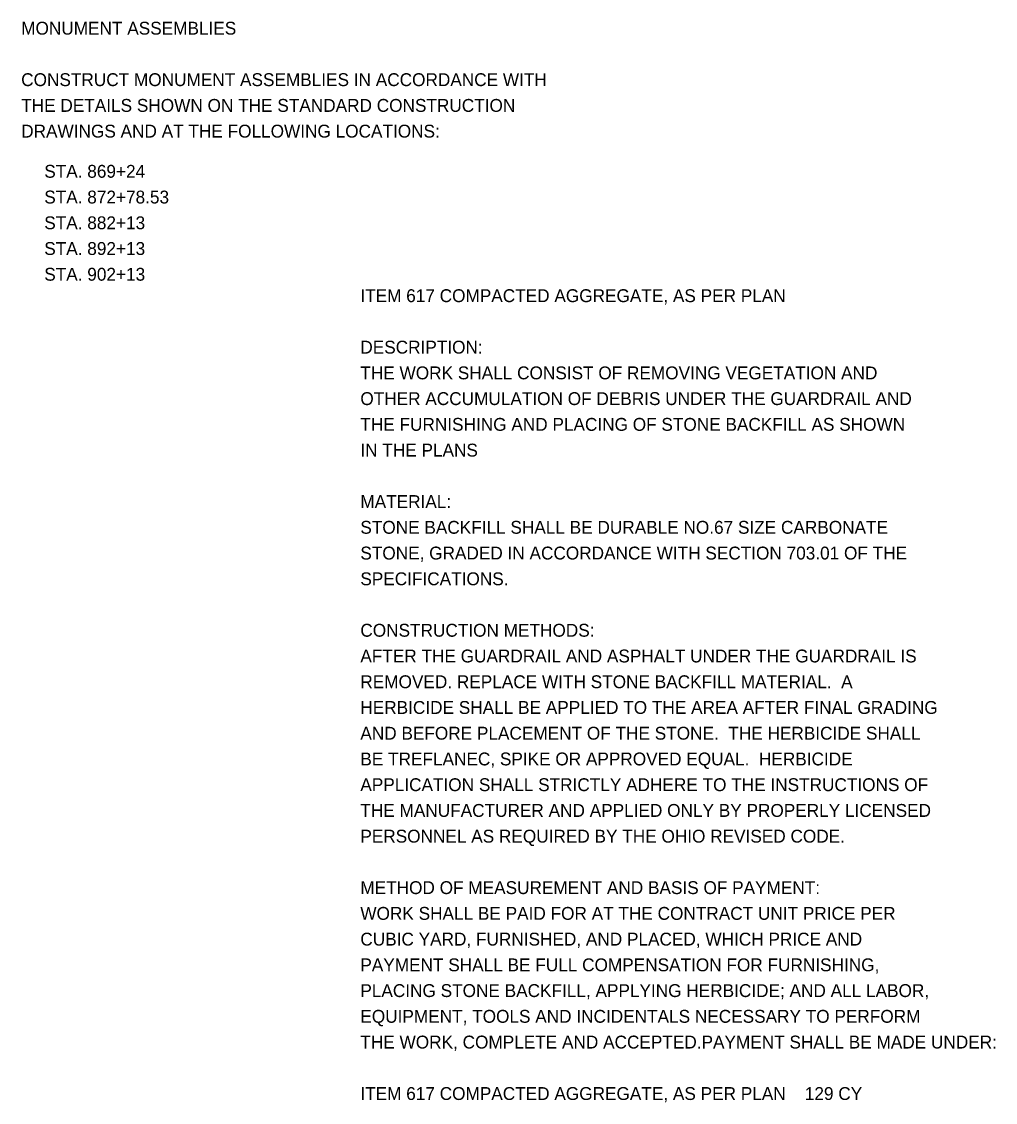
# Model space of a CAD drawing. Extents: x 0 to 46.4, y -1.7 to 22.
# Drawn here: x 35.79 to 46.39, y -1.72 to 10.04 of the extents above; entities that cross this region are included whole.
import ezdxf

# ---------------------------------------------------------------- set-up
doc = ezdxf.new("R2010")
doc.units = 0
doc.layers.add('SH_Text', color=7, linetype='Continuous')

msp = doc.modelspace()

# ---------------------------------------------------------------- texts
at = {"layer": 'SH_Text'}
for s, p in [('MONUMENT ASSEMBLIES', (35.783, 9.899)), ('CONSTRUCT MONUMENT ASSEMBLIES IN ACCORDANCE WITH', (35.783, 9.339)), ('THE DETAILS SHOWN ON THE STANDARD CONSTRUCTION', (35.783, 9.059)), ('DRAWINGS AND AT THE FOLLOWING LOCATIONS:', (35.783, 8.779)), ('STA. 869+24', (36.034, 8.342)), ('STA. 872+78.53', (36.034, 8.062)), ('STA. 882+13', (36.034, 7.782)), ('STA. 892+13', (36.034, 7.502)), ('STA. 902+13', (36.034, 7.222)), ('ITEM 617 COMPACTED AGGREGATE, AS PER PLAN', (39.474, 6.989)), ('DESCRIPTION:', (39.474, 6.429)), ('THE WORK SHALL CONSIST OF REMOVING VEGETATION AND', (39.474, 6.149)), ('OTHER ACCUMULATION OF DEBRIS UNDER THE GUARDRAIL AND', (39.474, 5.869)), ('THE FURNISHING AND PLACING OF STONE BACKFILL AS SHOWN', (39.474, 5.589)), ('IN THE PLANS', (39.474, 5.309)), ('MATERIAL:', (39.474, 4.749)), ('STONE BACKFILL SHALL BE DURABLE NO.67 SIZE CARBONATE', (39.474, 4.469)), ('STONE, GRADED IN ACCORDANCE WITH SECTION 703.01 OF THE', (39.474, 4.189)), ('SPECIFICATIONS.', (39.474, 3.909)), ('CONSTRUCTION METHODS:', (39.474, 3.349)), ('AFTER THE GUARDRAIL AND ASPHALT UNDER THE GUARDRAIL IS', (39.474, 3.069)), ('REMOVED. REPLACE WITH STONE BACKFILL MATERIAL.  A', (39.474, 2.789)), ('HERBICIDE SHALL BE APPLIED TO THE AREA AFTER FINAL GRADING', (39.474, 2.509)), ('AND BEFORE PLACEMENT OF THE STONE.  THE HERBICIDE SHALL', (39.474, 2.229)), ('BE TREFLANEC, SPIKE OR APPROVED EQUAL.  HERBICIDE', (39.474, 1.949)), ('APPLICATION SHALL STRICTLY ADHERE TO THE INSTRUCTIONS OF', (39.474, 1.669)), ('THE MANUFACTURER AND APPLIED ONLY BY PROPERLY LICENSED', (39.474, 1.389)), ('PERSONNEL AS REQUIRED BY THE OHIO REVISED CODE.', (39.474, 1.109)), ('METHOD OF MEASUREMENT AND BASIS OF PAYMENT:', (39.474, 0.549)), ('WORK SHALL BE PAID FOR AT THE CONTRACT UNIT PRICE PER', (39.474, 0.269)), ('CUBIC YARD, FURNISHED, AND PLACED, WHICH PRICE AND', (39.474, -0.011)), ('PAYMENT SHALL BE FULL COMPENSATION FOR FURNISHING,', (39.474, -0.291)), ('PLACING STONE BACKFILL, APPLYING HERBICIDE; AND ALL LABOR,', (39.474, -0.571)), ('EQUIPMENT, TOOLS AND INCIDENTALS NECESSARY TO PERFORM', (39.474, -0.851)), ('THE WORK, COMPLETE AND ACCEPTED.PAYMENT SHALL BE MADE UNDER:', (39.474, -1.131)), ('ITEM 617 COMPACTED AGGREGATE, AS PER PLAN    129 CY', (39.474, -1.691))]:
    msp.add_text(s, height=0.14, dxfattribs=at).set_placement(p)

doc.saveas('drawing.dxf')
